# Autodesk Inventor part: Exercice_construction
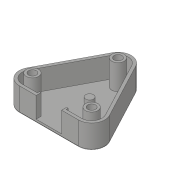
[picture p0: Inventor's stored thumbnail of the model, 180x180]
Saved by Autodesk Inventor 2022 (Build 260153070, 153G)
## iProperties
Created: 2018-06
Part Number: Exercice_construction
Material: Plastique ABS
Document SubType Name: Modeling
Designer: Fabian Perrée
Density: 1.06 g/cm^3
Appearance: Gris clair
Mass: 7.82351 g
Surface Area: 92.0535 cm^2
Volume: 7.38067 cm^3
Author: Fabian Perrée
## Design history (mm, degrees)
sketch "Esquisse1"
  geometry: L1 (0, 0)-(0, -59.098); L2 (0, 0)-(7.75, 0); L3 (25.07, -11.743)-(7.07, -45.743); L4 (-7.07, -45.743)-(-25.07, -11.743); L5 (-18, 0)-(-7.75, 0); L6 (14.25, -19.25)-(11, -19.25); L7 (9, -21.25)-(14.25, -21.25); L8 (14.25, -21.25)-(14.25, -19.25); L9 (11, -19.25)-(11, -16); L10 (11, -16)-(9, -16); L11 (9, -16)-(9, -21.25); L12 (-23.524, -10.924)-(-5.524, -44.924); L13 (5.524, -44.924)-(23.524, -10.924); L14 (7.75, 0)-(7.75, -3); L15 (7.75, -3)-(8.75, -3); L16 (8.75, -3)-(8.75, -1.75); L17 (-7.75, -3)-(-8.75, -3); L18 (-8.75, -3)-(-8.75, -1.75); L19 (-7.75, 0)-(-7.75, -3); L20 (18, -1.75)-(8.75, -1.75); L21 (-8.75, -1.75)-(-18, -1.75); L22 (7.75, 0)-(18, 0); L23 (-7.75, 0)-(0, 0); C1 r 2.375 at (18, -8); C2 r 2.375 at (-18, -8); C3 r 2.375 at (0, -42); C4 r 3.75 at (18, -8); C5 r 3.75 at (0, -42); C6 r 3.75 at (-18, -8); C7 r 2.375 at (0, -24.75); A1 r 8 centre (18, -8) between (25.07, -11.743) and (18, 0); A2 r 8 centre (0, -42) between (-7.07, -45.743) and (7.07, -45.743); A3 r 8 centre (-18, -8) between (-18, 0) and (-25.07, -11.743); A4 r 6.25 centre (-18, -8) between (-18, -1.75) and (-23.524, -10.924); A5 r 6.25 centre (0, -42) between (-5.524, -44.924) and (5.524, -44.924); A6 r 6.25 centre (18, -8) between (23.524, -10.924) and (18, -1.75); 1 further point
  constraints: 46 end point, 13 centre point, 12 point on circle, 10 tangent, 8 perpendicular, 7 point on line, 6 equal radius, 4 horizontal, 4 symmetric about line, 3 coincident, 3 vertical, 2 concentric, 1 parallel, 6 other
  dimensions: "d0" = 34 vertical distance of C3.centre C1.centre; "d1" = 2 distance of L7.end L6.start; "d2" = 3.25 distance of L6.end L9.end; "d3" = 9 distance between parallel lines of L1 L11; "d4" = 13.25 distance from line of C1.centre L7; "d5" = 8 radius of A1; "d6" = 7.5 diameter of C4; "d7" = 36 distance of C2.centre C1.centre; "d8" = 4.75 diameter of C1; "d9" = 4.75 diameter of C7; "d10" = 16.75 vertical distance of C1.centre C7.centre; "d11" = 1.75 radial gap between concentric circles of A1 A6; "d12" = 1 distance of L14.end L15.end; "d13" = 15.5 diameter of L14 L1; "d14" = 3 distance of L2.end L14.end; "d41" = 5.25 distance of L10.end L7.start
extrude "Extrusion1" new body sketch "Esquisse1" distance "d15" = 1.75; taper "d16" = 0 deg
extrude "Extrusion2" join sketch "Esquisse1" distance "d17" = 12.5; taper "d18" = 0 deg
extrude "Extrusion3" join sketch "Esquisse1" distance "d19" = 15.25; taper "d20" = 0 deg
extrude "Extrusion4" join sketch "Esquisse1" distance "d21" = 3.25; taper "d22" = 0 deg
node "Plan de construction1"
fillet "Congé1" dims "d40" = 0.5
node "Solide1"
other parameters: "d23" = 3.25
